Omron CX-Programmer project NuevoProyecto (CX-Programmer 9.50)

# PLC NewPLC1: CP1L-E EM

## Program P19_1 (cyclic task 0)
Local symbols
B1 100.00 BOOL
B2 100.01 BOOL
B3 100.02 BOOL
DN1 0.00 BOOL
DN2 0.01 BOOL
DN3 0.02 BOOL
Etapa_0 10.00 BOOL
Etapa_1 10.01 BOOL
Etapa_10 10.04 BOOL
Etapa_11 10.05 BOOL
Etapa_12 10.06 BOOL
Etapa_13 10.07 BOOL
Etapa_2 10.02 BOOL
Etapa_20 10.08 BOOL
Etapa_21 10.09 BOOL
Etapa_22 10.10 BOOL
Etapa_23 10.11 BOOL
Etapa_3 10.03 BOOL

### Section Sección1_Programa_principal
; Etapas X0, X1, X2, X3   +   X10, X11, X12, X13   +   X20, X21, X22, X23

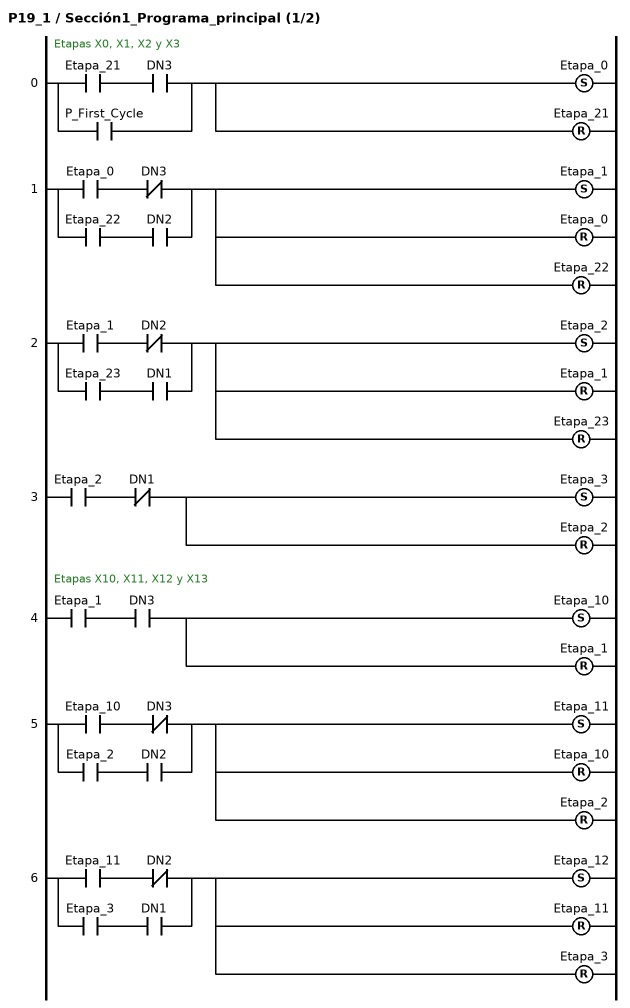
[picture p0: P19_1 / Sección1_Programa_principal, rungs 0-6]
; rung 0: Etapas X0, X1, X2 y X3
LD Etapa_21
AND DN3
OR P_First_Cycle
SET Etapa_0
RSET Etapa_21
; rung 1
LD Etapa_0
ANDNOT DN3
LD Etapa_22
AND DN2
ORLD
SET Etapa_1
RSET Etapa_0
RSET Etapa_22
; rung 2
LD Etapa_1
ANDNOT DN2
LD Etapa_23
AND DN1
ORLD
SET Etapa_2
RSET Etapa_1
RSET Etapa_23
; rung 3
LD Etapa_2
ANDNOT DN1
SET Etapa_3
RSET Etapa_2
; rung 4: Etapas X10, X11, X12 y X13
LD Etapa_1
AND DN3
SET Etapa_10
RSET Etapa_1
; rung 5
LD Etapa_10
ANDNOT DN3
LD Etapa_2
AND DN2
ORLD
SET Etapa_11
RSET Etapa_10
RSET Etapa_2
; rung 6
LD Etapa_11
ANDNOT DN2
LD Etapa_3
AND DN1
ORLD
SET Etapa_12
RSET Etapa_11
RSET Etapa_3

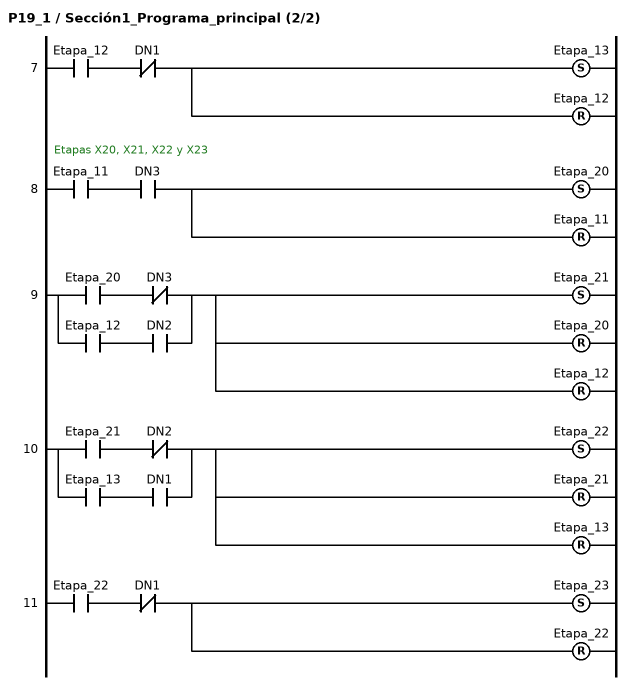
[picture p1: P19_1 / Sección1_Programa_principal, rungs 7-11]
; rung 7
LD Etapa_12
ANDNOT DN1
SET Etapa_13
RSET Etapa_12
; rung 8: Etapas X20, X21, X22 y X23
LD Etapa_11
AND DN3
SET Etapa_20
RSET Etapa_11
; rung 9
LD Etapa_20
ANDNOT DN3
LD Etapa_12
AND DN2
ORLD
SET Etapa_21
RSET Etapa_20
RSET Etapa_12
; rung 10
LD Etapa_21
ANDNOT DN2
LD Etapa_13
AND DN1
ORLD
SET Etapa_22
RSET Etapa_21
RSET Etapa_13
; rung 11
LD Etapa_22
ANDNOT DN1
SET Etapa_23
RSET Etapa_22

### Section Sección2_Salidas

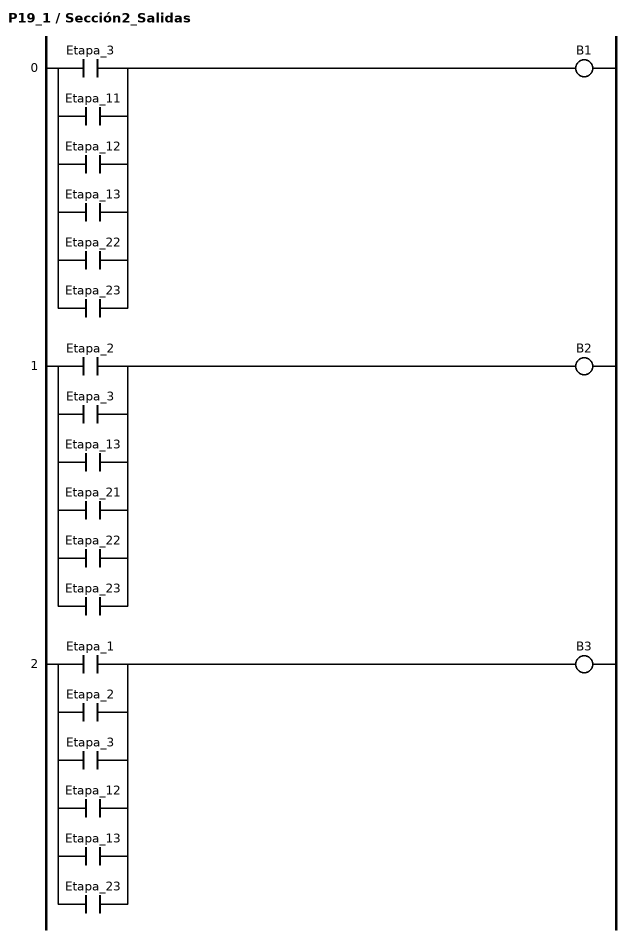
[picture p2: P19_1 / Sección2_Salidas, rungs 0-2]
; rung 0
LD Etapa_3
OR Etapa_11
OR Etapa_12
OR Etapa_13
OR Etapa_22
OR Etapa_23
OUT B1
; rung 1
LD Etapa_2
OR Etapa_3
OR Etapa_13
OR Etapa_21
OR Etapa_22
OR Etapa_23
OUT B2
; rung 2
LD Etapa_1
OR Etapa_2
OR Etapa_3
OR Etapa_12
OR Etapa_13
OR Etapa_23
OUT B3

### Section Sección3_END
; rung 0: Fin de programa
END(001)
